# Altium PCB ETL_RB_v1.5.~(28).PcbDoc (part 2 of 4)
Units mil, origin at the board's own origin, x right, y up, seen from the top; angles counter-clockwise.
Board outline 5129.92 x 2224.41 mil, 8 copper layers (Top Layer, plane 1, M1, plane 2, plane 3, M2, plane 4, Bottom Layer), stack 36.907 mil thick; 212 components, 186 nets, 1961 pads, 978 vias.
Unrouted connection lines stored in the file: 395.
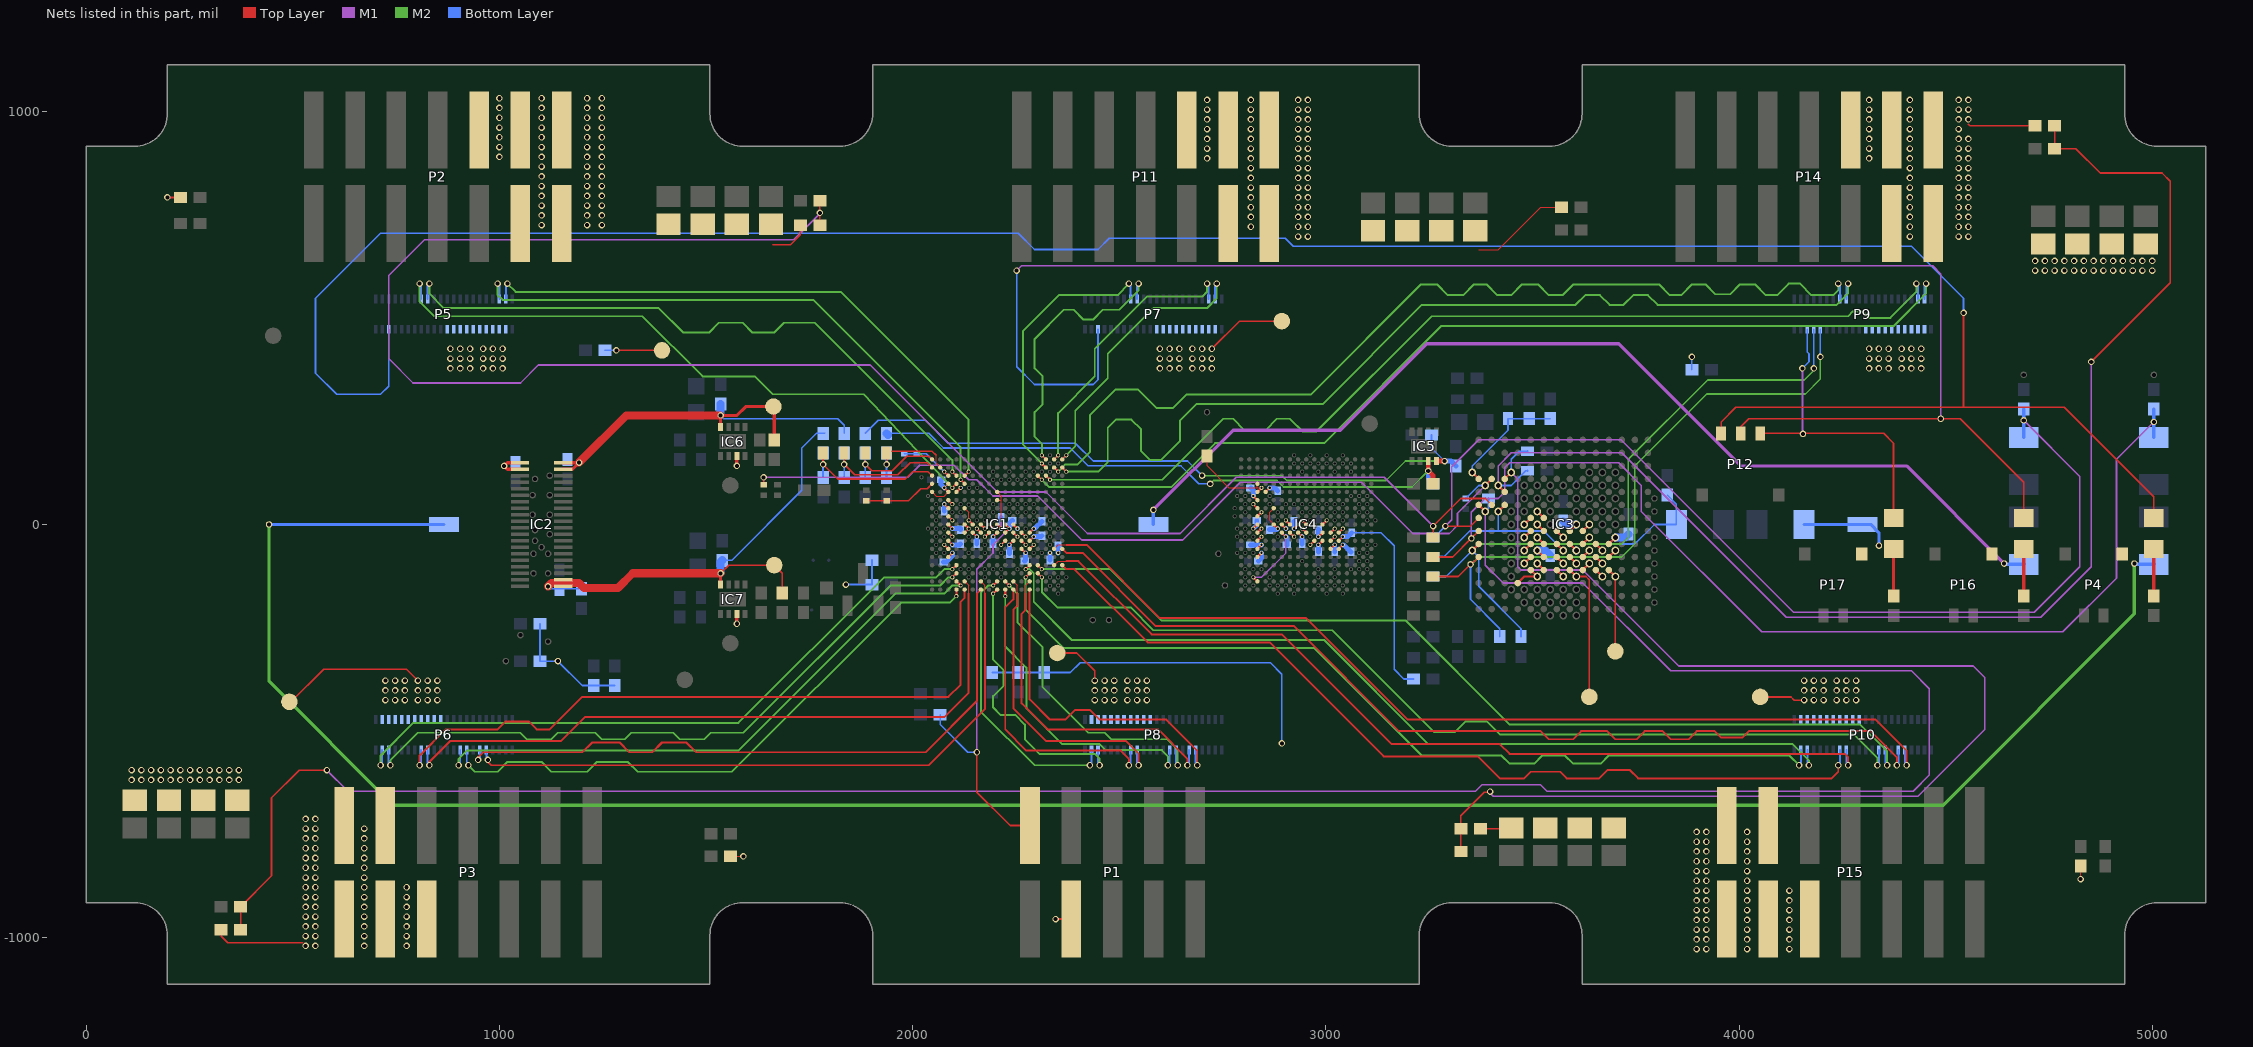
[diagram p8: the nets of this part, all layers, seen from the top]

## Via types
v1: diameter 15.75, hole 9.84, Top Layer to Bottom Layer, 978 vias

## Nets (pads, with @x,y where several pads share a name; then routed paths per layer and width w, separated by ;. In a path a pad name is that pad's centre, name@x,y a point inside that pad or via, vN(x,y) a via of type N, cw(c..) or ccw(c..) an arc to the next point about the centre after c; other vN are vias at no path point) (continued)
1V2_mon4: C205.2 IC3.P10 P9.17 pad.1@3350.39,-96.46 R211.2 | length 1597.8
  Top Layer w4: C205.2@3259.84,-125.98 3320.87,-125.98 pad.1@3350.39,-96.46 3352.36,-96.46 IC3.P10@3370.08,-78.74
  M2 w4: pad.1@3350.39,-96.46 3352.36,-96.46 3370.08,-78.74 3716.54,-78.74 3748.03,-47.24 3748.03,141.73 3922,315.7 4160.68,315.7 4196.85,351.87 v1(4196.85,405.51)
  Bottom Layer w4: pad.1@3350.39,-96.46 3350.39,-181.1 3421.26,-251.97 R211.2@3421.26,-271.65 ; v1(4196.85,405.51) P9.17@4196.85,472.44
1V2_mon5: C206.2 IC3.P9 P9.18 pad.1@3354.33,-62.99 R213.2 | length 1618.2
  Top Layer w5.12: pad.1@3354.33,-62.99 IC3.P9@3370.08,-47.24
  M2 w4: pad.1@3354.33,-62.99 3370.08,-47.24 3716.54,-47.24 3732.28,-31.5 3732.28,157.48 3924.46,349.65 4158.22,349.65 4181.1,372.54 v1(4181.1,377.95)
  Bottom Layer w4: C206.2@3259.84,-125.98 3291.34,-125.98 pad.1@3354.33,-62.99 3370.08,-78.74 3370.08,-149.61 3472.44,-251.97 R213.2@3472.44,-271.65 ; v1(4181.1,377.95) P9.18@4181.1,472.44
1V2_RB: C111.1 C112.1 C113.1 C114.1 C115.1 C116.1 C117.1 C118.1 C119.1 C120.1 C121.1 C122.1 C123.1 C124.1 C125.1 C126.1 C127.1 C128.1 C129.1 C130.1 C131.1 C132.1 C133.1 C134.1 C135.1 C160.1 C162.1 C163.1 C164.1 C165.1 C166.1 C167.1 C168.1 IC1.D3 IC1.E1 IC1.E3 IC1.E4 IC1.E9 IC1.F3 IC1.F9 IC1.G3 IC1.G5 IC1.H3 IC1.J3 IC1.J5 IC1.J6 IC1.J7 IC1.J8 IC1.J9 IC1.J11 IC1.K3 IC1.K5 IC1.K6 IC1.K7 IC1.K8 IC1.K9 IC1.K11 IC1.K12 IC1.K13 IC1.L3 IC1.L10 IC1.L11 IC1.L12 IC1.L13 IC1.M3 IC1.M12 IC1.M13 IC1.N3 IC2.38 IC2.40 IC4.D3 IC4.E3 IC4.E4 IC4.F3 IC4.G3 IC4.G5 IC4.H3 IC4.J3 IC4.J5 IC4.J6 IC4.J7 IC4.J8 IC4.J9 IC4.J11 IC4.K3 IC4.K6 IC4.K7 IC4.K8 IC4.K9 IC4.K11 IC4.K12 IC4.K13 IC4.L3 IC4.L10 IC4.L11 IC4.L12 IC4.L13 IC4.M3 IC4.M12 IC4.M13 IC4.N3 IC4.T3 IC6.3 IC7.3 P1.8 P11.10 P11.11 P11.12 P11.13 P11.14 pad.1@1011.81,141.73 pad.1@1141.73,-330.71 pad.1@2076.77,49.21 pad.1@2076.77,88.58 pad.1@2076.77,-49.21 pad.1@2096.46,9.84 pad.1@2096.46,49.21 pad.1@2096.46,-9.84 pad.1@2096.46,-29.53 pad.1@2096.46,-49.21 pad.1@2096.46,-68.9 pad.1@2116.14,88.58 pad.1@2135.83,9.84 pad.1@2135.83,-9.84 pad.1@2155.51,-9.84 pad.1@2155.51,-29.53 pad.1@2175.2,-9.84 pad.1@2175.2,-29.53 pad.1@2194.88,-9.84 pad.1@2194.88,-29.53 pad.1@2214.57,-9.84 pad.1@2214.57,-49.21 pad.1@2234.25,-49.21 pad.1@2253.94,-9.84 pad.1@2253.94,-29.53 pad.1@2273.62,-29.53 pad.1@2273.62,-49.21 pad.1@2273.62,-68.9 pad.1@2293.31,-9.84 pad.1@2293.31,-29.53 pad.1@2293.31,-49.21 pad.1@2332.68,-68.9 pad.1@2352.36,-68.9 pad.1@2824.8,49.21 pad.1@2824.8,68.9 pad.1@2824.8,-9.84 pad.1@2824.8,-127.95 pad.1@2844.49,29.53 pad.1@2844.49,88.58 pad.1@2844.49,-9.84 pad.1@2844.49,-29.53 pad.1@2844.49,-49.21 pad.1@2844.49,-68.9 pad.1@2864.17,88.58 pad.1@2883.86,-9.84 pad.1@2903.54,9.84 pad.1@2903.54,-9.84 pad.1@2903.54,-29.53 pad.1@2923.23,-9.84 pad.1@2923.23,-29.53 pad.1@2942.91,9.84 pad.1@2942.91,-9.84 pad.1@2942.91,-29.53 pad.1@2962.6,-49.21 pad.1@2982.28,-29.53 pad.1@2982.28,-49.21 pad.1@3001.97,9.84 pad.1@3021.65,-9.84 pad.1@3021.65,-29.53 pad.1@3021.65,-49.21 pad.1@3041.34,-9.84 pad.1@3041.34,-29.53 pad.1@3041.34,-49.21 R101.2 R102.1 R103.2 R104.2 R105.2 R106.2 R107.1 R109.2 R110.2 R202.2 R204.2 R206.2 R208.2 R210.2 R237.2 R238.2 R239.2 TP6.1 | length 4476.8
  Top Layer w3: R204.2@1559.06,-803.15 v1(1590.55,-803.15) ; IC1.E1@2047.24,78.74 2057.09,68.9 2076.77,68.9 IC1.E3@2086.61,78.74 ; pad.1@2076.77,88.58 IC1.D3@2086.61,98.43 ; IC1.K5@2125.98,-19.68 pad.1@2135.83,-9.84 ; IC1.G5@2125.98,39.37 2135.83,29.53 pad.1@2135.83,9.84 ; IC1.F9@2204.72,59.06 2214.57,59.06 ; IC1.E9@2204.72,78.74 2214.57,68.9 2214.57,59.06 ; pad.1@2214.57,-9.84 2214.57,59.06 ; v1(2346.46,-954.72) v1@2350.39,-954.72 ; R238.2@2712.6,165.35 2712.6,141.73 2765.75,88.58 2834.65,88.58 ; IC4.D3@2834.65,98.43 2834.65,88.58 ; pad.1@2844.49,88.58 2834.65,88.58 ; IC4.J5@2874.02,0 2864.17,9.84 2864.17,29.53 IC4.G5@2874.02,39.37 ; 3370.08,665.35 3417.32,665.35 3519.68,767.72 R206.2@3570.87,767.72 ; v1(4826.77,-858.27) R208.2@4826.77,-826.77
  Top Layer w4: v1(196.85,791.34) R202.2@228.35,791.34 ; v1(1283.46,421.26) TP6.1@1393.7,421.26
  Top Layer w4.02: v1(2346.46,-954.72) P1.8@2384.25,-954.72
  Top Layer w5.12: pad.1@2076.77,-49.21 IC1.M3@2086.61,-59.05 ; pad.1@2076.77,49.21 IC1.G3@2086.61,39.37 ; pad.1@2076.77,88.58 IC1.E3@2086.61,78.74 ; IC1.N3@2086.61,-78.74 pad.1@2096.46,-68.9 ; IC1.L3@2086.61,-39.37 pad.1@2096.46,-49.21 ; IC1.K3@2086.61,-19.68 pad.1@2096.46,-29.53 ; IC1.J3@2086.61,0 pad.1@2096.46,-9.84 ; IC1.H3@2086.61,19.69 pad.1@2096.46,9.84 ; IC1.F3@2086.61,59.06 pad.1@2096.46,49.21 ; IC1.E4@2106.3,78.74 pad.1@2116.14,88.58 ; IC1.J5@2125.98,0 pad.1@2135.83,-9.84 ; pad.1@2135.83,9.84 IC1.J6@2145.67,0 ; IC1.K6@2145.67,-19.68 pad.1@2155.51,-29.53 ; pad.1@2155.51,-9.84 IC1.K7@2165.35,-19.68 ; IC1.J7@2165.35,0 pad.1@2175.2,-9.84 ; pad.1@2175.2,-29.53 IC1.K8@2185.04,-19.68 ; IC1.J8@2185.04,0 pad.1@2194.88,-9.84 ; pad.1@2194.88,-29.53 IC1.K9@2204.72,-19.68 ; IC1.J9@2204.72,0 pad.1@2214.57,-9.84 ; pad.1@2214.57,-49.21 IC1.L10@2224.41,-39.37 ; pad.1@2234.25,-49.21 IC1.L11@2244.09,-39.37 ; IC1.K11@2244.09,-19.68 pad.1@2253.94,-29.53 ; IC1.J11@2244.09,0 pad.1@2253.94,-9.84 ; IC1.M12@2263.78,-59.05 pad.1@2273.62,-68.9 ; IC1.L12@2263.78,-39.37 pad.1@2273.62,-49.21 ; IC1.K12@2263.78,-19.68 pad.1@2273.62,-29.53 ; IC1.M13@2283.46,-59.05 pad.1@2293.31,-49.21 ; IC1.L13@2283.46,-39.37 pad.1@2293.31,-29.53 ; IC1.K13@2283.46,-19.68 pad.1@2293.31,-9.84 ; pad.1@2824.8,-127.95 IC4.T3@2834.65,-137.8 ; pad.1@2824.8,-9.84 IC4.J3@2834.65,0 ; pad.1@2824.8,49.21 IC4.G3@2834.65,39.37 ; pad.1@2824.8,68.9 IC4.F3@2834.65,59.05 ; IC4.N3@2834.65,-78.74 pad.1@2844.49,-68.9 ; IC4.M3@2834.65,-59.05 pad.1@2844.49,-49.21 ; IC4.L3@2834.65,-39.37 pad.1@2844.49,-29.53 ; IC4.K3@2834.65,-19.68 pad.1@2844.49,-9.84 ; IC4.H3@2834.65,19.68 pad.1@2844.49,29.53 ; IC4.E3@2834.65,78.74 pad.1@2844.49,88.58 ; IC4.E4@2854.33,78.74 pad.1@2864.17,88.58 ; IC4.J5@2874.02,0 pad.1@2883.86,-9.84 ; IC4.K6@2893.7,-19.68 pad.1@2903.54,-29.53 ; IC4.J6@2893.7,0 pad.1@2903.54,-9.84 ; pad.1@2903.54,9.84 IC4.J7@2913.39,0 ; IC4.K7@2913.39,-19.68 pad.1@2923.23,-29.53 ; pad.1@2923.23,-9.84 IC4.J8@2933.07,0 ; IC4.K8@2933.07,-19.68 pad.1@2942.91,-29.53 ; pad.1@2942.91,-9.84 IC4.K9@2952.76,-19.68 ; pad.1@2942.91,9.84 IC4.J9@2952.76,0 ; pad.1@2962.6,-49.21 IC4.L10@2972.44,-39.37 ; pad.1@2982.28,-49.21 IC4.L11@2992.13,-39.37 ; pad.1@2982.28,-29.53 IC4.K11@2992.13,-19.68 ; IC4.J11@2992.13,0 pad.1@3001.97,9.84 ; IC4.M12@3011.81,-59.05 pad.1@3021.65,-49.21 ; IC4.L12@3011.81,-39.37 pad.1@3021.65,-29.53 ; IC4.K12@3011.81,-19.68 pad.1@3021.65,-9.84 ; IC4.M13@3031.5,-59.05 pad.1@3041.34,-49.21 ; IC4.L13@3031.5,-39.37 pad.1@3041.34,-29.53 ; IC4.K13@3031.5,-19.68 pad.1@3041.34,-9.84
  Top Layer w7.87: IC2.38@1050,133.86 1019.69,133.86 pad.1@1011.81,141.73 1019.69,149.61 IC2.40@1050,149.61 ; v1(1574.8,-240.16) IC7.3@1574.8,-216.54 ; v1(1574.8,141.73) IC6.3@1574.8,165.35
  M1 w4: pad.1@2824.8,-127.95 2844.49,-127.95 2903.54,-68.9 pad.1@2903.54,-29.53
  Bottom Layer w3: C133.1@2817.32,88.58 C133.1@2818.9,88.58
  Bottom Layer w4: R239.2@1255.91,421.26 v1(1283.46,421.26) ; R110.2@2192.91,-358.27 R109.2@2255.91,-358.27 R210.2@2318.9,-358.27 2381.89,-358.27 2405.51,-334.65 2866.14,-334.65 2893.7,-362.2 v1(2893.7,-529.66) ; R237.2@3885.83,374.02 3885.83,377.95 v1(3885.83,405.51)
  Bottom Layer w4.02: R104.2@1098.43,-240.16 R103.2@1098.43,-330.71 pad.1@1141.73,-330.71 1200.79,-389.76 R105.2@1228.35,-389.76 R106.2@1279.53,-389.76 ; C166.1@3062.99,-20.08 3063.39,-19.68 3133.86,-19.68 3165.35,-51.18 3165.35,-350.39 3188.98,-374.02 R107.1@3212.6,-374.02
  Bottom Layer w5.12: v1(1838.58,-145.67) R101.2@1901.57,-145.67 R102.1@1901.57,-86.61 ; pad.1@2824.8,-9.84 pad.1@2826.77,-7.87
  Bottom Layer w7.87: pad.1@2116.14,88.58 pad.1@2117.72,88.58 ; C113.1@2352.36,-51.57 2353.94,-51.57 C113.1@2354.33,-51.18
  Bottom Layer w11.81: C119.1@2069.29,108.27 2069.29,96.06 pad.1@2076.77,88.58 ; C125.1@2075.2,-90.55 2082.68,-90.55 2096.46,-76.77 pad.1@2096.46,-68.9 ; C116.1@2076.77,31.89 pad.1@2076.77,49.21 ; pad.1@2096.46,-49.21 2113.78,-49.21 C117.1@2116.14,-46.85 ; pad.1@2096.46,-9.84 2116.14,-9.84 C126.1@2116.14,-12.2 ; C114.1@2155.51,-46.85 pad.1@2155.51,-29.53 ; C122.1@2194.88,-46.85 pad.1@2194.88,-29.53 ; pad.1@2214.57,-9.84 C120.1@2214.57,17.32 ; C118.1@2234.25,-70.47 pad.1@2234.25,-49.21 ; C123.1@2271.65,-88.58 C123.1@2271.26,-88.58 2273.62,-86.22 pad.1@2273.62,-68.9 ; pad.1@2293.31,-29.53 2310.63,-29.53 C115.1@2312.99,-27.17 ; pad.1@2293.31,-9.84 2295.67,-9.84 2299.56,-5.95 2299.85,-5.95 2309.1,3.3 2309.1,3.59 C124.1@2312.99,7.48 ; C121.1@2332.68,-86.22 pad.1@2332.68,-68.9 ; pad.1@2352.36,-68.9 C113.1@2352.36,-51.57 ; C130.1@2817.32,-49.21 pad.1@2844.49,-49.21 ; C133.1@2818.9,88.58 2824.8,82.68 pad.1@2824.8,68.9 ; pad.1@2826.77,-7.87 2833.07,-1.57 C164.1@2833.07,9.84 ; C132.1@2837.01,-88.58 2844.49,-81.1 pad.1@2844.49,-68.9 ; C163.1@2864.17,-12.2 2881.5,-12.2 pad.1@2883.86,-9.84 ; pad.1@2864.17,88.58 2876.38,88.58 C167.1@2883.86,81.1 ; pad.1@2903.54,-29.53 2905.91,-31.89 C168.1@2905.91,-49.21 ; pad.1@2923.23,-9.84 C129.1@2923.23,7.48 ; C128.1@2942.91,-46.85 pad.1@2942.91,-29.53 ; C134.1@2982.28,-66.54 pad.1@2982.28,-49.21 ; pad.1@2982.28,-29.53 C131.1@2982.28,-12.2 ; C165.1@3021.65,-66.54 pad.1@3021.65,-49.21 ; pad.1@3041.34,-49.21 3043.31,-49.21 3061.02,-66.93 C135.1@3061.02,-66.54 ; pad.1@3041.34,-29.53 3053.54,-29.53 C166.1@3062.99,-20.08
  other v1: 2933.07,696.85 2956.69,696.85 2818.9,720.47 2933.07,720.47 2956.69,720.47 2818.9,744.09 2933.07,744.09 2956.69,744.09 2818.9,767.72 2933.07,767.72 2956.69,767.72 2818.9,791.34 2933.07,791.34 2956.69,791.34 2818.9,814.96 2933.07,814.96 2956.69,814.96 2818.9,838.58 2933.07,838.58 2956.69,838.58 2818.9,862.2 2933.07,862.2 2956.69,862.2 2712.6,885.83 2818.9,885.83 2933.07,885.83 2956.69,885.83 2712.6,909.45 2818.9,909.45 2933.07,909.45 2956.69,909.45 2712.6,933.07 2818.9,933.07 2933.07,933.07 2956.69,933.07 2712.6,956.69 2818.9,956.69 2933.07,956.69 2956.69,956.69 2712.6,980.32 2818.9,980.32 2933.07,980.32 2956.69,980.32 2712.6,1003.94 2818.9,1003.94 2933.07,1003.94 2956.69,1003.94 2712.6,1027.56 2818.9,1027.56 2933.07,1027.56 2956.69,1027.56
1V2A: C218.1 C219.1 C220.1 C221.1 P2.10 P2.11 P2.12 P2.13 P2.14 P5.1 P5.2 P5.3 P5.4 P5.5 P5.6 P5.7 P5.8 P5.9 P5.10 P6.6 P6.7 P6.8 P6.9 P6.10 R214.2 TP1.1 | length 455.4
  Top Layer w4: TP1.1@492.13,-429.13 496.06,-429.13 574.8,-350.39 775.59,-350.39 v1(803.15,-377.95) ; 1661.42,677.17 1704.72,677.17 1728.35,700.79 R214.2@1728.35,724.41
  other v1: 803.15,-425.2 826.77,-425.2 850.39,-425.2 803.15,-401.57 826.77,-401.57 850.39,-401.57 826.77,-377.95 850.39,-377.95 881.89,377.95 905.51,377.95 929.13,377.95 960.63,377.95 984.25,377.95 1007.87,377.95 881.89,401.57 905.51,401.57 929.13,401.57 960.63,401.57 984.25,401.57 1007.87,401.57 881.89,425.2 905.51,425.2 929.13,425.2 960.63,425.2 984.25,425.2 1007.87,425.2 1102.36,724.41 1212.6,724.41 1248.03,724.41 1102.36,748.03 1212.6,748.03 1248.03,748.03 1102.36,771.65 1212.6,771.65 1248.03,771.65 1102.36,795.28 1212.6,795.28 1248.03,795.28 1102.36,818.9 1212.6,818.9 1248.03,818.9 1102.36,842.52 1212.6,842.52 1248.03,842.52 1102.36,866.14 1212.6,866.14 1248.03,866.14 1000,889.76 1102.36,889.76 1212.6,889.76 1248.03,889.76 1000,913.39 1102.36,913.39 1212.6,913.39 1248.03,913.39 1000,937.01 1102.36,937.01 1212.6,937.01 1248.03,937.01 1000,960.63 1102.36,960.63 1212.6,960.63 1248.03,960.63 1000,984.25 1102.36,984.25 1212.6,984.25 1248.03,984.25 1000,1007.87 1102.36,1007.87 1212.6,1007.87 1248.03,1007.87 1000,1031.5 1102.36,1031.5 1212.6,1031.5 1248.03,1031.5
1V2B: C222.1 C223.1 C224.1 C225.1 P3.10 P3.11 P3.12 P3.13 P3.14 P6.1 P6.2 P6.3 P6.4 P6.5 P8.1 P8.2 P8.3 P8.4 P8.5 P8.6 P8.7 P8.8 P8.9 P8.10 R216.2 TP2.1 | length 351.2
  Top Layer w4: TP2.1@2350.39,-311.02 2397.64,-311.02 2440.94,-354.33 v1(2440.94,-377.95)
  Top Layer w4.02: R216.2@326.77,-980.32 326.77,-996.06 342.52,-1011.81 523.62,-1011.81
  other v1: 531.5,-1019.68 555.12,-1019.68 673.23,-1019.68 775.59,-1019.68 531.5,-996.06 555.12,-996.06 673.23,-996.06 775.59,-996.06 531.5,-972.44 555.12,-972.44 673.23,-972.44 775.59,-972.44 531.5,-948.82 555.12,-948.82 673.23,-948.82 775.59,-948.82 531.5,-925.2 555.12,-925.2 673.23,-925.2 775.59,-925.2 531.5,-901.57 555.12,-901.57 673.23,-901.57 775.59,-901.57 531.5,-877.95 555.12,-877.95 673.23,-877.95 775.59,-877.95 531.5,-854.33 555.12,-854.33 673.23,-854.33 531.5,-830.71 555.12,-830.71 673.23,-830.71 531.5,-807.09 555.12,-807.09 673.23,-807.09 531.5,-783.46 555.12,-783.46 673.23,-783.46 531.5,-759.84 555.12,-759.84 673.23,-759.84 531.5,-736.22 555.12,-736.22 673.23,-736.22 531.5,-712.6 555.12,-712.6 110.24,-618.11 133.86,-618.11 157.48,-618.11 181.1,-618.11 204.72,-618.11 228.35,-618.11 251.97,-618.11 275.59,-618.11 299.21,-618.11 322.83,-618.11 346.46,-618.11 370.08,-618.11 110.24,-594.49 133.86,-594.49 157.48,-594.49 181.1,-594.49 204.72,-594.49 228.35,-594.49 251.97,-594.49 275.59,-594.49 299.21,-594.49 322.83,-594.49 346.46,-594.49 370.08,-594.49 724.41,-425.2 748.03,-425.2 771.65,-425.2 2440.94,-425.2 2464.57,-425.2 2488.19,-425.2 2519.69,-425.2 2543.31,-425.2 2566.93,-425.2 724.41,-401.57 748.03,-401.57 771.65,-401.57 2440.94,-401.57 2464.57,-401.57 2488.19,-401.57 2519.69,-401.57 2543.31,-401.57 2566.93,-401.57 724.41,-377.95 748.03,-377.95 771.65,-377.95 2464.57,-377.95 2488.19,-377.95 2519.69,-377.95 2543.31,-377.95 2566.93,-377.95
1V2C: C226.1 C227.1 C228.1 C229.1 P7.1 P7.2 P7.3 P7.4 P7.5 P7.6 P7.7 P7.8 P7.9 P7.10 P9.1 P9.2 P9.3 P9.4 P9.5 P14.10 P14.11 P14.12 P14.13 P14.14 R218.2 TP3.1 | length 360.1
  Top Layer w4: v1(2724.41,425.2) 2791.34,492.13 TP3.1@2893.7,492.13 ; 4555.12,968.5 4559.06,964.57 R218.2@4716.54,964.57
  other v1: 2598.43,377.95 2622.05,377.95 2645.67,377.95 2677.17,377.95 2700.79,377.95 2724.41,377.95 4393.7,377.95 4417.32,377.95 4440.94,377.95 2598.43,401.57 2622.05,401.57 2645.67,401.57 2677.17,401.57 2700.79,401.57 2724.41,401.57 4393.7,401.57 4417.32,401.57 4440.94,401.57 2598.43,425.2 2622.05,425.2 2645.67,425.2 2677.17,425.2 2700.79,425.2 4393.7,425.2 4417.32,425.2 4440.94,425.2 4716.54,614.17 4740.16,614.17 4763.78,614.17 4787.4,614.17 4811.02,614.17 4834.65,614.17 4858.27,614.17 4881.89,614.17 4905.51,614.17 4929.13,614.17 4952.76,614.17 4976.38,614.17 5000,614.17 4716.54,637.8 4740.16,637.8 4763.78,637.8 4787.4,637.8 4811.02,637.8 4834.65,637.8 4858.27,637.8 4881.89,637.8 4905.51,637.8 4929.13,637.8 4952.76,637.8 4976.38,637.8 5000,637.8 4413.39,696.85 4531.5,696.85 4555.12,696.85 4413.39,720.47 4531.5,720.47 4555.12,720.47 4413.39,744.09 4531.5,744.09 4555.12,744.09 4413.39,767.72 4531.5,767.72 4555.12,767.72 4413.39,791.34 4531.5,791.34 4555.12,791.34 4413.39,814.96 4531.5,814.96 4555.12,814.96 4413.39,838.58 4531.5,838.58 4555.12,838.58 4413.39,862.2 4531.5,862.2 4555.12,862.2 4314.96,885.83 4413.39,885.83 4531.5,885.83 4555.12,885.83 4314.96,909.45 4413.39,909.45 4531.5,909.45 4555.12,909.45 4314.96,933.07 4413.39,933.07 4531.5,933.07 4555.12,933.07 4314.96,956.69 4413.39,956.69 4531.5,956.69 4314.96,980.32 4413.39,980.32 4531.5,980.32 4555.12,980.32 4314.96,1003.94 4413.39,1003.94 4531.5,1003.94 4555.12,1003.94 4314.96,1027.56 4413.39,1027.56 4531.5,1027.56 4555.12,1027.56
1V2D: C230.1 C231.1 C232.1 C233.1 P9.6 P9.7 P9.8 P9.9 P9.10 P10.1 P10.2 P10.3 P10.4 P10.5 P10.6 P10.7 P10.8 P10.9 P10.10 P15.10 P15.11 P15.12 P15.13 P15.14 R220.2 TP4.1 | length 185.2
  Top Layer w4: R220.2@3374.02,-736.22 3446.85,-736.22 C233.1@3448.82,-734.25 ; TP4.1@4051.18,-417.32 4125.98,-417.32 4133.86,-425.2 v1(4157.48,-425.2)
  other v1: 3897.64,-1027.56 3921.26,-1027.56 4019.69,-1027.56 4122.05,-1027.56 3897.64,-1003.94 3921.26,-1003.94 4019.69,-1003.94 4122.05,-1003.94 3897.64,-980.32 3921.26,-980.32 4019.69,-980.32 4122.05,-980.32 3897.64,-956.69 3921.26,-956.69 4019.69,-956.69 4122.05,-956.69 3897.64,-933.07 3921.26,-933.07 4019.69,-933.07 4122.05,-933.07 3897.64,-909.45 3921.26,-909.45 4019.69,-909.45 4122.05,-909.45 3897.64,-885.83 3921.26,-885.83 4019.69,-885.83 4122.05,-885.83 3897.64,-862.2 3921.26,-862.2 4019.69,-862.2 3897.64,-838.58 3921.26,-838.58 4019.69,-838.58 3897.64,-814.96 3921.26,-814.96 4019.69,-814.96 3897.64,-791.34 3921.26,-791.34 4019.69,-791.34 3897.64,-767.72 3921.26,-767.72 4019.69,-767.72 3897.64,-744.09 3921.26,-744.09 4019.69,-744.09 4181.1,-425.2 4204.72,-425.2 4236.22,-425.2 4259.84,-425.2 4283.46,-425.2 4157.48,-401.57 4181.1,-401.57 4204.72,-401.57 4236.22,-401.57 4259.84,-401.57 4283.46,-401.57 4157.48,-377.95 4181.1,-377.95 4204.72,-377.95 4236.22,-377.95 4259.84,-377.95 4283.46,-377.95 4314.96,377.95 4338.58,377.95 4362.2,377.95 4314.96,401.57 4338.58,401.57 4362.2,401.57 4314.96,425.2 4338.58,425.2 4362.2,425.2
1V5A: C138.1 C139.1 IC3.D9 IC3.D10 IC3.D11 IC3.E9 IC3.E10 IC3.E11 IC3.F8 IC3.F9 IC3.F10 IC3.F11 IC3.J7 IC3.J8 IC3.J9 IC3.J10 IC3.J11 IC3.K7 IC3.K8 IC3.K9 IC3.K10 IC3.K11 IC3.L12 IC5.7 pad.1@2720.47,98.43 pad.1@3480.31,0 pad.1@3480.31,-31.5 pad.1@3480.32,-62.99 pad.1@3480.32,-94.49 pad.1@3511.81,0 pad.1@3511.81,31.5 pad.1@3511.81,-31.5 pad.1@3511.81,-62.99 pad.1@3511.81,-94.49 pad.1@3511.81,-125.98 pad.1@3637.8,0 pad.1@3637.8,-31.5 pad.1@3637.8,-62.99 pad.1@3637.8,-94.49 pad.1@3669.29,-62.99 pad.1@3669.29,-94.49 pad.1@3669.29,-125.98 pad.1@3700.79,-31.5 pad.1@3700.79,-62.99 pad.1@3700.79,-125.98 R113.1 R128.1 R133.2 TP7.1 | length 2249.9
  Top Layer w4: TP7.1@3700.79,-307.09 pad.1@3700.79,-125.98
  Top Layer w5.12: IC3.L12@3464.57,-141.73 3480.31,-125.98 pad.1@3511.81,-125.98 IC3.K11@3496.06,-110.24 ; pad.1@3480.32,-94.49 IC3.K10@3496.06,-78.74 ; pad.1@3480.32,-62.99 IC3.K9@3496.06,-47.24 ; pad.1@3480.31,-31.5 IC3.K8@3496.06,-15.75 ; pad.1@3480.31,0 IC3.K7@3496.06,15.75 ; pad.1@3511.81,-94.49 IC3.J11@3527.56,-110.24 ; pad.1@3511.81,-62.99 IC3.J10@3527.56,-78.74 ; pad.1@3511.81,-31.5 IC3.J9@3527.56,-47.24 ; pad.1@3511.81,0 IC3.J8@3527.56,-15.75 ; pad.1@3511.81,31.5 IC3.J7@3527.56,15.75 ; IC3.F11@3622.05,-110.24 pad.1@3637.8,-94.49 ; IC3.F10@3622.05,-78.74 pad.1@3637.8,-62.99 ; IC3.F9@3622.05,-47.24 pad.1@3637.8,-31.5 ; IC3.F8@3622.05,-15.75 pad.1@3637.8,0 ; IC3.E11@3653.54,-110.24 pad.1@3669.29,-125.98 ; IC3.E10@3653.54,-78.74 pad.1@3669.29,-94.49 ; IC3.E9@3653.54,-47.24 pad.1@3669.29,-62.99 ; IC3.D11@3685.04,-110.24 pad.1@3700.79,-125.98 ; IC3.D10@3685.04,-78.74 pad.1@3700.79,-62.99 ; IC3.D9@3685.04,-47.24 pad.1@3700.79,-31.5
  Top Layer w11.81: IC5.7@3248.03,153.54 v1(3248.03,129.92) 3259.84,118.11 R113.1@3259.84,98.43 R113.1@3263.78,102.36
  M2 w4: pad.1@2720.47,98.43 2728.35,106.3 2881.89,106.3 2897.64,90.55 3208.66,90.55 v1(3248.03,129.92)
  Bottom Layer w4: R133.2@1940.94,216.54 1944.88,220.47 2039.37,220.47 2074.8,185.04 2381.89,185.04 2425.2,141.73 2649.61,141.73 2692.91,98.43 pad.1@2720.47,98.43
  Bottom Layer w11.81: v1(3248.03,129.92) 3248.03,110.24 R128.1@3259.84,98.43 R128.1@3263.78,102.36
  Bottom Layer w18.9: R133.2@1937.01,220.47 R133.2@1940.94,216.54 ; pad.1@3511.81,-62.99 3531.5,-62.99 C138.1@3543.31,-74.8 ; pad.1@3700.79,-31.5 3724.41,-31.5 C139.1@3732.28,-23.62
1V5D: C140.1 IC3.G8 IC3.G9 IC3.G10 IC3.G11 IC3.H8 IC3.H9 IC3.H10 IC3.H11 IC5.8 pad.1@2700.79,118.11 pad.1@3574.8,-31.5 pad.1@3574.8,-62.99 pad.1@3574.8,-94.49 pad.1@3574.8,-125.98 pad.1@3606.3,0 pad.1@3606.3,-62.99 pad.1@3606.3,-94.49 pad.1@3606.3,-125.98 R111.1 R117.2 R127.1 TP8.1 | length 2153.9
  Top Layer w4: pad.1@3606.3,-125.98 3629.92,-125.98 3637.8,-133.86 TP8.1@3637.8,-417.32
  Top Layer w5.12: IC3.H11@3559.05,-110.24 pad.1@3574.8,-125.98 ; IC3.H10@3559.05,-78.74 pad.1@3574.8,-94.49 ; IC3.H9@3559.05,-47.24 pad.1@3574.8,-62.99 ; IC3.H8@3559.05,-15.75 pad.1@3574.8,-31.5 ; IC3.G11@3590.55,-110.24 pad.1@3606.3,-125.98 ; IC3.G10@3590.55,-78.74 pad.1@3606.3,-94.49 ; IC3.G9@3590.55,-47.24 pad.1@3606.3,-62.99 ; IC3.G8@3590.55,-15.75 pad.1@3606.3,0
  Top Layer w11.81: IC5.8@3267.72,153.54 v1(3287.4,153.54)
  M2 w4: pad.1@2700.79,118.11 2893.7,118.11 2905.51,106.3 3145.67,106.3 3192.91,153.54 v1(3287.4,153.54)
  Bottom Layer w4: R117.2@1885.83,220.47 1917.32,251.97 2031.5,251.97 2086.61,196.85 2393.7,196.85 2437.01,153.54 2665.35,153.54 pad.1@2700.79,118.11 ; R127.1@3255.91,216.54 3255.91,185.04 v1(3287.4,153.54)
  Bottom Layer w11.81: v1(3287.4,153.54) 3303.15,153.54 R111.1@3314.96,141.73
  Bottom Layer w18.9: C140.1@3574.8,7.87 3582.68,0 pad.1@3606.3,0
2V5F: C136.1 IC1.J10 IC1.K10 P1.9 pad.1@2234.25,-9.84 R132.1 | length 1023.1
  Top Layer w4: v1(2155.51,-551.18) 2155.51,-647.64 2236.22,-728.35 P1.9@2284.25,-728.35
  Top Layer w5.12: IC1.K10@2224.41,-19.68 pad.1@2234.25,-9.84 IC1.J10@2224.41,0
  M1 w4: v1(2155.51,-551.18) 2155.51,-108.27 2194.88,-68.9 2194.88,-49.21 pad.1@2234.25,-9.84
  Bottom Layer w4: R132.1@2066.93,-460.63 2066.93,-484.25 2133.86,-551.18 v1(2155.51,-551.18)
  Bottom Layer w11.81: pad.1@2234.25,-9.84 2234.25,2.36 C136.1@2241.73,9.84
2V5RX: C154.1 IC2.1 IC2.3 IC7.8 pad.1@1118.11,-149.61 R124.1 R125.2 R135.2 R148.2 TP9.1 | length 1236.3
  Top Layer w4: v1(1535.43,-118.11) 1555.12,-98.43 TP9.1@1665.35,-98.43 1685.04,-118.11 R124.1@1685.04,-165.35
  Top Layer w7.87: IC7.8@1535.43,-145.67 v1(1535.43,-118.11)
  Top Layer w19.68: pad.1@1118.11,-149.61 1125.98,-141.73 1192.91,-141.73 1204.72,-153.54 1287.4,-153.54 1322.83,-118.11 v1(1535.43,-118.11)
  Bottom Layer w4: pad.1@1118.11,-149.61 1124.02,-155.51 R148.2@1198.82,-155.51 ; R125.2@1539.37,-86.61 1562.99,-86.61 1732.28,82.68 1732.28,185.04 1767.72,220.47 R135.2@1783.46,220.47 ; R135.2@1783.46,220.47 1787.4,220.47 R135.2@1783.46,220.47
  Bottom Layer w19.68: v1(1535.43,-118.11) 1535.43,-90.55 R125.2@1539.37,-86.61
2V5TX: C153.1 IC2.37 IC2.39 IC6.8 R114.2 R116.1 R119.2 TP10.1 | length 1075
  Top Layer w7.87: IC2.37@1154.72,133.86 1177.17,133.86 v1(1192.91,149.61) IC2.39@1154.72,149.61 ; IC6.8@1535.43,236.22 v1(1535.43,263.78) 1574.8,263.78 1596.46,285.43 TP10.1@1663.39,285.43 1665.35,283.46 R116.1@1665.35,204.72
  Top Layer w19.68: v1(1192.91,149.61) 1307.09,263.78 v1(1535.43,263.78)
  Bottom Layer w4: v1(1535.43,263.78) 1543.31,255.91 1818.9,255.91 1834.65,240.16 R119.2@1834.65,220.47
  Bottom Layer w19.68: v1(1535.43,263.78) R114.2@1535.43,291.34
ADC1: C109.1 IC1.A1 R117.1 R118.2 | length 272.5
  Top Layer w3: v1(1885.83,145.67) C109.1@1885.83,173.23
  Top Layer w4: v1(1885.83,145.67) 1901.57,129.92 1950.79,129.92 1986.22,165.35 2039.37,165.35 IC1.A1@2047.24,157.48
  Bottom Layer w4: R118.2@1885.83,114.17 v1(1885.83,145.67) R117.1@1885.83,173.23
ADC2: C141.1 IC1.B2 R133.1 R134.2 | length 246
  Top Layer w3: v1(1937.01,145.67) C141.1@1937.01,173.23 ; 2057.09,167.32 2057.09,147.64 IC1.B2@2066.93,137.8
  Top Layer w4: C141.1@1937.01,173.23 1940.94,177.17 2047.24,177.17 2057.09,167.32
  Bottom Layer w4: R134.2@1937.01,114.17 v1(1937.01,145.67) R133.1@1937.01,173.23
ADC3: C150.1 IC1.B1 R119.1 R120.2 | length 326.9
  Top Layer w4: C150.1@1834.65,173.23 v1(1834.65,145.67) 1860.24,120.08 1964.57,120.08 1994.09,149.61 2035.43,149.61 IC1.B1@2047.24,137.8
  Bottom Layer w4: R120.2@1834.65,114.17 v1(1834.65,145.67) R119.1@1834.65,173.23
ADC4: IC1.C3 pad.1@2076.77,127.95 R146.2 R147.1 | length 128.3
  Top Layer w5.12: pad.1@2076.77,127.95 IC1.C3@2086.61,118.11
  Bottom Layer w4: R147.1@1980.31,171.26 R146.2@2009.84,171.26 2033.46,171.26 pad.1@2076.77,127.95
ADC6: C151.1 IC1.C1 R122.2 R135.1 | length 376.5
  Top Layer w4: C151.1@1783.46,173.23 v1(1783.46,145.67) 1818.9,110.24 1982.28,110.24 2000,127.95 2037.4,127.95 IC1.C1@2047.24,118.11
  Bottom Layer w4: R122.2@1783.46,114.17 v1(1783.46,145.67) R135.1@1783.46,173.23
ADC7: IC1.D1 R145.1 RT1.2 | length 176.6
  Top Layer w4: RT1.2@1887.8,57.09 R145.1@1937.01,57.09 1990.16,57.09 2019.69,86.61 2035.43,86.61 IC1.D1@2047.24,98.43
ADC_IN18: C207.2 IC3.P8 pad.1@3352.36,-33.46 pad.1@5003.94,248.03 R222.1 R223.2 | length 2589.3
  Top Layer w4: C207.2@3259.84,-78.74 3307.09,-78.74 pad.1@3352.36,-33.46 IC3.P8@3370.08,-15.75
  M1 w4: pad.1@3352.36,-33.46 3352.36,29.53 3385.83,62.99 3417.32,62.99 3433.07,78.74 3433.07,137.8 3444.88,149.61 3708.66,149.61 3763.78,94.49 3763.78,31.5 4055.12,-259.84 4783.46,-259.84 4913.39,-129.92 4913.39,157.48 pad.1@5003.94,248.03
  Bottom Layer w8: R222.1@5003.94,210.63 R223.2@5003.94,279.53
ADC_IN21: C208.2 IC3.P7 pad.1@4688.98,251.97 R224.1 R225.2 | length 2524.6
  Top Layer w4.02: v1(3289.37,-3.94) 3350.39,-3.94 IC3.P7@3370.08,15.75
  M1 w4.02: v1(3289.37,-3.94) 3305.12,11.81 3305.12,139.76 3370.08,204.72 3714.57,204.72 4131.89,-212.6 4714.57,-212.6 4824.8,-102.36 4824.8,116.14 pad.1@4688.98,251.97
  Bottom Layer w4.02: C208.2@3259.84,-31.5 3261.81,-31.5 v1(3289.37,-3.94)
  Bottom Layer w8: R224.1@4688.98,210.63 R225.2@4688.98,279.53
ADC_IN22: C209.2 IC3.M6 pad.1@3417.32,31.5 R226.1 R227.2 | length 799.4
  Top Layer w5.12: pad.1@3417.32,31.5 IC3.M6@3433.07,47.24
  Bottom Layer w4: C209.2@3259.84,-78.74 3259.84,-76.77 3283.46,-76.77 3285.43,-78.74 3348.43,-15.75 3417.32,-15.75 ; pad.1@3417.32,31.5 3417.32,-15.75 ; R227.2@3826.77,70.87 3848.43,49.21 R226.1@3848.43,0 3795.28,0 3748.03,-47.24 3559.06,-47.24 3527.56,-15.75 3417.32,-15.75
ADC_IN23: C210.2 IC3.N6 R214.1 R215.2 | length 4413.5
  Top Layer w4: R214.1@1775.59,724.41 v1(1775.59,753.94) R215.2@1775.59,783.46 ; C210.2@3259.84,-31.5 v1(3259.84,-3.94) ; v1@3260.61,-3.17 3326.77,62.99 3385.83,62.99 IC3.N6@3401.57,47.24
  M1 w4: v1(1775.59,753.94) 1775.59,751.97 1712.6,688.98 818.9,688.98 732.28,602.36 732.28,401.57 791.34,342.52 1051.18,342.52 1094.49,385.83 1897.64,385.83 2204.72,78.74 2322.83,78.74 2423.23,-21.65 2647.64,-21.65 2783.46,114.17 3141.73,114.17 v1(3259.84,-3.94)
ADC_IN24: C211.2 IC3.P6 pad.1@3385.83,31.5 R216.1 R217.2 | length 6034.3
  Top Layer w4.02: R216.1@374.02,-980.32 R217.2@374.02,-925.2 448.82,-850.39 448.82,-661.42 515.75,-594.49 v1(582.68,-594.49)
  Top Layer w5.12: IC3.P6@3370.08,47.24 pad.1@3385.83,31.5
  M1 w4.02: v1(582.68,-594.49) 633.86,-645.67 3362.2,-645.67 3377.95,-629.92 3519.69,-629.92 3535.43,-645.67 4421.26,-645.67 4460.63,-606.3 4460.63,-397.64 4417.32,-354.33 3834.65,-354.33 3622.05,-141.73 3429.13,-141.73 3385.83,-98.43 pad.1@3385.83,31.5
  Bottom Layer w4: pad.1@3385.83,31.5 3393.7,39.37 C211.2@3393.7,62.99
ADC_IN25: C212.2 IC3.M5 pad.1@3417.32,94.49 R218.1 R219.2 | length 3197.8
  Top Layer w4.02: R218.1@4763.78,964.57 R219.2@4763.78,909.45 4814.96,909.45 4874.02,850.39 5023.62,850.39 5043.31,830.71 5043.31,584.65 v1(4852.36,393.7)
  Top Layer w5.12: pad.1@3417.32,94.49 IC3.M5@3433.07,78.74
  M1 w4.02: pad.1@3417.32,94.49 3417.32,141.73 3448.82,173.23 3716.54,173.23 4114.17,-224.41 4730.32,-224.41 4852.36,-102.36 v1(4852.36,393.7)
  Bottom Layer w4.02: pad.1@3417.32,94.49 3448.82,94.49 3484.25,129.92 C212.2@3488.19,129.92
ADC_IN28: C213.2 IC3.M4 pad.1@3448.82,125.98 R220.1 R221.2 | length 3154.6
  Top Layer w4.02: R221.2@3326.77,-791.34 R220.1@3326.77,-736.22 3326.77,-704.72 3383.74,-647.76 3396.43,-647.76 v1(3397.64,-646.54)
  Top Layer w5.12: IC3.M4@3433.07,110.24 pad.1@3448.82,125.98
  M1 w4.02: v1(3397.64,-646.54) 3397.64,-649.61 3405.51,-657.48 4433.07,-657.48 4594.49,-496.06 4594.49,-370.08 4566.93,-342.52 3854.33,-342.52 3622.05,-110.24 3472.44,-110.24 3464.57,-102.36 3464.57,110.24 pad.1@3448.82,125.98
  Bottom Layer w4.02: pad.1@3448.82,125.98 3448.82,157.48 3468.5,177.17 C213.2@3488.19,177.17
ADC_IN29: IC3.N4 pad.1@3385.83,94.49 R243.1 RT2.2 | length 2108.3
  Top Layer w4.02: R243.1@1639.76,96.46 v1(1639.76,114.17)
  Top Layer w5.12: pad.1@3385.83,94.49 IC3.N4@3401.57,110.24
  M1 w4.02: v1(1639.76,114.17) 1988.19,114.17 2017.72,143.7 2100.39,143.7 2135.83,108.27 2155.51,108.27 2194.88,68.9 2303.15,68.9 2409.45,-37.4 2653.54,-37.4 2793.31,102.36 3086.61,102.36 3210.63,-21.65 3299.21,-21.65 3318.9,-1.97 3318.9,27.56 pad.1@3385.83,94.49
  Bottom Layer w4.02: RT2.2@3338.58,62.99 3370.08,94.49 pad.1@3385.83,94.49
ADC_IN30: C214.2 IC3.P4 pad.1@3354.33,125.98 R228.1 R229.2 | length 290.4
  Top Layer w5.12: pad.1@3354.33,125.98 IC3.P4@3370.08,110.24
  Bottom Layer w4.02: pad.1@3354.33,125.98 3354.33,141.73 3440.94,228.35 C214.2@3440.94,255.91 R228.1@3543.31,255.91
AGND0: C215.2 P5.19 P12.3 | length 6161
  Top Layer w4: P12.3@3956.69,220.47 3956.69,248.03 3992.13,283.46 4543.31,283.46 ; v1(4543.31,511.81) 4543.31,283.46 ; C215.2@5003.94,15.75 5003.94,66.93 4787.4,283.46 4543.31,283.46
  Bottom Layer w4: P5.19@732.28,472.44 732.28,334.65 712.6,314.96 606.3,314.96 555.12,366.14 555.12,547.24 712.6,704.72 2255.91,704.72 2295.28,665.35 2448.82,665.35 2476.38,692.91 2901.57,692.91 2921.26,673.23 4417.32,673.23 4543.31,547.24 v1(4543.31,511.81)
AGND1: C216.2 P7.19 P12.2 pad.1@4488.19,255.91 | length 4032.8
  Top Layer w4: P12.2@4003.94,220.47 4003.94,236.22 4023.62,255.91 pad.1@4488.19,255.91 4535.43,255.91 4688.98,102.36 C216.2@4688.98,15.75
  M1 w4: v1(2251.97,614.17) 2263.78,625.98 4468.5,625.98 4488.19,606.3 pad.1@4488.19,255.91
  Bottom Layer w4: v1(2251.97,614.17) 2251.97,381.89 2295.28,338.58 2437.01,338.58 2448.82,350.39 P7.19@2448.82,472.44
AGND2: C217.2 P9.19 P12.1 pad.1@4154.77,219.24 | length 776.8
  Top Layer w4: P12.1@4051.18,220.47 4153.54,220.47 4350.39,220.47 4374.02,196.85 C217.2@4374.02,15.75 ; pad.1@4154.77,219.24 pad.1@4154.77,220.47
  M1 w4: v1(4153.54,377.95) 4153.54,220.47 pad.1@4154.77,219.24
  Bottom Layer w4: v1(4153.54,377.95) 4169.29,393.7 4169.29,413.39 4165.35,417.32 P9.19@4165.35,472.44
BV0: C215.1 CT1.1 P4.3 pad.1@442.91,0 pad.1@4956.69,-94.49 R230.1 R240.2 | length 5916.8
  Top Layer w8: R230.1@5003.94,-173.23 C215.1@5003.94,-59.06
  M2 w8: pad.1@442.91,0 442.91,-379.92 742.13,-679.13 4494.09,-679.13 4956.69,-216.54 pad.1@4956.69,-94.49
  Bottom Layer w8: pad.1@442.91,0 CT1.1@866.14,0 ; pad.1@4956.69,-94.49 4958.66,-96.46 R240.2@5003.94,-96.46
BV1: C216.1 CT2.1 P16.3 pad.1@2582.68,35.43 pad.1@4641.73,-94.49 R231.1 R241.2 | length 2643.2
  Top Layer w8: R231.1@4688.98,-173.23 C216.1@4688.98,-59.06
  M1 w8: pad.1@2582.68,35.43 2775.59,228.35 3035.43,228.35 3244.09,437.01 3708.66,437.01 4003.94,141.73 4405.51,141.73 pad.1@4641.73,-94.49
  Bottom Layer w8: CT2.1@2582.68,0 pad.1@2582.68,35.43 ; pad.1@4641.73,-94.49 4643.7,-96.46 R241.2@4688.98,-96.46
BV2: C217.1 CT3.1 P17.3 pad.1@4338.58,-51.18 R232.1 R242.2 | length 338.9
  Top Layer w8: R232.1@4374.02,-173.23 C217.1@4374.02,-59.06
  Bottom Layer w3: pad.1@4338.58,-55.12 pad.1@4338.58,-51.18
  Bottom Layer w8: R242.2@4157.48,0 CT3.1@4299.21,0 4318.9,0 4338.58,-19.68 pad.1@4338.58,-51.18
ECLK0N: IC1.U4 P6.27 pad.1@2106.3,-173.23 | length 1457.7
  Top Layer w5.12: pad.1@2106.3,-173.23 IC1.U4@2106.3,-157.48
  M2 w4.72: v1(925.2,-582.68) 940.94,-598.43 996.06,-598.43 1019.69,-574.8 1102.36,-574.8 1125.98,-598.43 1212.6,-598.43 1236.22,-574.8 1311.02,-574.8 1334.65,-598.43 1562.99,-598.43 1972.44,-188.98 2090.55,-188.98 pad.1@2106.3,-173.23
  Bottom Layer w4.72: P6.27@921.26,-545.28 921.26,-578.74 v1(925.2,-582.68)
ECLK0P: IC1.T4 P6.28 pad.1@2116.14,-147.64 | length 1456.9
  Top Layer w5.12: IC1.T4@2106.3,-137.79 pad.1@2116.14,-147.64
  M2 w4.72: v1(901.57,-582.68) 901.57,-566.93 921.26,-547.24 1578.74,-547.24 1958.66,-167.32 2076.77,-167.32 2096.46,-147.64 pad.1@2116.14,-147.64
  Bottom Layer w4.72: v1(901.57,-582.68) 905.51,-578.74 P6.28@905.51,-545.28
ECLK1N: IC1.R4 P6.39 pad.1@2096.46,-127.95 | length 1647.6
  Top Layer w5.12: pad.1@2096.46,-127.95 IC1.R4@2106.3,-118.11
  M2 w4.72: v1(736.22,-582.68) 736.22,-570.87 803.15,-503.94 1051.18,-503.94 1066.93,-519.68 1125.98,-519.68 1141.73,-503.94 1232.28,-503.94 1248.03,-519.68 1303.15,-519.68 1318.9,-503.94 1421.26,-503.94 1437.01,-519.68 1496.06,-519.68 1511.81,-503.94 1590.55,-503.94 1946.85,-147.64 2066.93,-147.64 2086.61,-127.95 pad.1@2096.46,-127.95
  Bottom Layer w4.72: P6.39@732.28,-545.28 732.28,-578.74 v1(736.22,-582.68)
ECLK1P: IC1.P4 P6.40 pad.1@2096.46,-108.27 | length 1647.2
  Top Layer w5.12: pad.1@2096.46,-108.27 IC1.P4@2106.3,-98.42
  M2 w4.72: v1(712.6,-582.68) 712.6,-559.06 791.34,-480.32 1578.74,-480.32 1931.1,-127.95 2057.09,-127.95 2076.77,-108.27 ; 2076.77,-108.27 pad.1@2096.46,-108.27
  Bottom Layer w4.72: v1(712.6,-582.68) 716.54,-578.74 P6.40@716.54,-545.28
ECLK2N: IC1.U9 P8.39 pad.1@2194.88,-167.32 | length 695.5
  Top Layer w5.12: pad.1@2194.88,-167.32 IC1.U9@2204.72,-157.48
  M2 w4.72: pad.1@2194.88,-167.32 2194.88,-326.77 2220.47,-352.36 2220.47,-389.76 2194.88,-415.35 2194.88,-442.91 2212.6,-460.63 2248.03,-460.63 2271.65,-484.25 2271.65,-519.68 2307.09,-555.12 2440.94,-555.12 2452.76,-566.93 v1(2452.76,-582.68)
  Bottom Layer w4.72: P8.39@2448.82,-545.28 2448.82,-578.74 v1(2452.76,-582.68)
ECLK2P: IC1.T9 P8.40 pad.1@2194.88,-147.64 | length 694.8
  Top Layer w5.12: pad.1@2194.88,-147.64 IC1.T9@2204.72,-137.79
  M2 w4.72: pad.1@2194.88,-147.64 2183.07,-147.64 2165.35,-165.35 2165.35,-452.76 2295.28,-582.68 v1(2429.13,-582.68)
  Bottom Layer w4.72: v1(2429.13,-582.68) 2433.07,-578.74 P8.40@2433.07,-545.28
ECLK3N: IC1.U10 P8.28 pad.1@2224.41,-173.23 | length 759.9
  Top Layer w5.12: pad.1@2224.41,-173.23 IC1.U10@2224.41,-157.48
  M2 w4.72: pad.1@2224.41,-173.23 2224.41,-295.28 2275.59,-346.46 2275.59,-444.88 2362.2,-531.5 2452.76,-531.5 2467.52,-546.26 2603.35,-546.26 2618.11,-561.02 v1(2618.11,-582.68)
  Bottom Layer w4.72: v1(2618.11,-582.68) 2622.05,-578.74 P8.28@2622.05,-545.28
ECLK3P: IC1.T10 P8.27 pad.1@2234.25,-147.64 | length 759.4
  Top Layer w5.12: IC1.T10@2224.41,-137.79 pad.1@2234.25,-147.64
  M2 w4.72: pad.1@2234.25,-147.64 2253.94,-167.32 2253.94,-236.22 2314.96,-297.24 2314.96,-393.7 2425.2,-503.94 2464.57,-503.94 2480.31,-519.68 2616.14,-519.68 2641.73,-545.28 v1(2641.73,-582.68)
  Bottom Layer w4.72: P8.27@2637.8,-545.28 2637.8,-578.74 v1(2641.73,-582.68)
ECLK4N: IC1.R13 P10.40 pad.1@2273.62,-127.95 | length 2192.1
  Top Layer w5.12: pad.1@2273.62,-127.95 IC1.R13@2283.46,-118.11
  M2 w4.72: pad.1@2273.62,-127.95 2273.62,-206.69 2366.14,-299.21 2972.44,-299.21 3232.28,-559.06 3425.2,-559.06 3444.88,-578.74 3503.94,-578.74 3523.62,-559.06 3578.74,-559.06 3598.43,-578.74 3665.35,-578.74 3685.04,-559.06 4122.05,-559.06 v1(4145.67,-582.68)
  Bottom Layer w4.72: v1(4145.67,-582.68) 4149.61,-578.74 P10.40@4149.61,-545.28
ECLK4P: IC1.P13 P10.39 pad.1@2273.62,-108.27 | length 2192.4
  Top Layer w5.12: pad.1@2273.62,-108.27 IC1.P13@2283.46,-98.42
  M2 w4.72: pad.1@2273.62,-108.27 2283.46,-108.27 2293.31,-118.11 2293.31,-187.01 2385.83,-279.53 2996.06,-279.53 3248.03,-531.5 4129.92,-531.5 4169.29,-570.87 v1(4169.29,-582.68)
  Bottom Layer w4.72: P10.39@4165.35,-545.28 4165.35,-578.74 v1(4169.29,-582.68)
ECLK5N: IC1.R14 P10.28 pad.1@2312.99,-127.95 | length 2315.3
  Top Layer w5.12: IC1.R14@2303.15,-118.11 pad.1@2312.99,-127.95
  M2 w4.72: pad.1@2312.99,-127.95 2312.99,-163.39 2350.39,-200.79 2527.56,-200.79 2582.68,-255.91 3015.75,-255.91 3261.81,-501.97 3312.99,-501.97 3338.58,-476.38 3389.76,-476.38 3421.26,-507.87 4277.56,-507.87 4334.65,-564.96 v1(4334.65,-582.68)
  Bottom Layer w4.72: v1(4334.65,-582.68) 4338.58,-578.74 P10.28@4338.58,-545.28
ECLK5P: IC1.P14 P10.27 pad.1@2312.99,-108.27 | length 2314.3
  Top Layer w5.12: IC1.P14@2303.15,-98.42 pad.1@2312.99,-108.27
  M2 w4.72: pad.1@2312.99,-108.27 2478.35,-108.27 2602.36,-232.28 3192.91,-232.28 3444.88,-484.25 4293.31,-484.25 4358.27,-549.21 v1(4358.27,-582.68)
  Bottom Layer w4.72: P10.27@4354.33,-545.28 4354.33,-578.74 v1(4358.27,-582.68)
ECLK22N: IC1.B17 P9.28 pad.1@2372.05,127.95 | length 2376.5
  Top Layer w5.12: IC1.B17@2362.2,137.8 pad.1@2372.05,127.95
  M2 w4.72: pad.1@2372.05,127.95 2449.8,127.95 2472.44,150.59 2472.44,234.25 2492.13,253.94 2529.53,253.94 2553.15,230.32 2553.15,177.17 2574.8,155.51 2600.39,155.51 2647.64,202.76 2647.64,251.97 2687.01,291.34 2992.13,291.34 3232.28,531.5 3604.33,531.5 3627.95,555.12 3663.39,555.12 3687.01,531.5 3720.47,531.5 3744.09,555.12 3779.53,555.12 3803.15,531.5 4236.22,531.5 4263.78,559.06 v1(4263.78,582.68)
  Bottom Layer w4.72: P9.28@4259.84,545.28 4259.84,578.74 v1(4263.78,582.68)
ECLK22P: IC1.B16 P9.27 pad.1@2352.36,127.95 | length 2376.1
  Top Layer w5.12: IC1.B16@2342.52,137.8 pad.1@2352.36,127.95
  M2 w4.72: pad.1@2352.36,127.95 2370.08,145.67 2399.61,145.67 2429.13,175.2 2429.13,263.78 2492.13,326.77 2545.28,326.77 2590.55,281.5 2629.92,281.5 2663.39,314.96 2964.57,314.96 3230.32,580.71 3269.69,580.71 3295.28,555.12 3332.68,555.12 3358.27,580.71 3389.76,580.71 3415.35,555.12 3448.82,555.12 3474.41,580.71 3513.78,580.71 3539.37,555.12 3572.83,555.12 3598.43,580.71 3807.09,580.71 3832.68,555.12 3860.24,555.12 3885.83,580.71 3919.29,580.71 3942.91,557.09 3978.35,557.09 4001.97,580.71 4039.37,580.71 4064.96,555.12 4092.52,555.12 4120.08,582.68 4147.64,582.68 4175.2,555.12 4228.35,555.12 4240.16,566.93 v1(4240.16,582.68)
  Bottom Layer w4.72: v1(4240.16,582.68) 4244.09,578.74 P9.27@4244.09,545.28
ECLK23N: IC1.A17 P7.40 pad.1@2372.05,167.32 | length 695.3
  Top Layer w5.12: IC1.A17@2362.2,157.48 pad.1@2372.05,167.32
  M2 w4.72: pad.1@2372.05,167.32 2393.7,188.98 2393.7,275.59 2472.44,354.33 2472.44,413.39 2582.68,523.62 2712.6,523.62 2736.22,547.24 v1(2736.22,582.68)
  Bottom Layer w4.72: P7.40@2732.28,545.28 2732.28,578.74 v1(2736.22,582.68)
ECLK23P: IC1.A16 P7.39 pad.1@2352.36,167.32 | length 695.9
  Top Layer w5.12: IC1.A16@2342.52,157.48 pad.1@2352.36,167.32
  M2 w4.72: pad.1@2352.36,167.32 2352.36,269.68 2440.94,358.27 2440.94,425.2 2566.93,551.18 2700.79,551.18 2712.6,562.99 v1(2712.6,582.68)
  Bottom Layer w4.72: v1(2712.6,582.68) 2716.54,578.74 P7.39@2716.54,545.28
ECLK24N: IC1.C15 P9.39 pad.1@2332.68,108.27 | length 2419.4
  Top Layer w5.12: IC1.C15@2322.83,118.11 pad.1@2332.68,108.27
  M2 w4.72: pad.1@2332.68,108.27 2604.33,108.27 2751.97,255.91 2775.59,255.91 2803.15,228.35 2854.33,228.35 2881.89,255.91 2913.39,255.91 2944.88,224.41 2976.38,224.41 3255.91,503.94 4263.78,503.94 4275.59,515.75 4299.21,515.75 4314.96,500 4366.14,500 4429.13,562.99 v1(4429.13,582.68)
  Bottom Layer w4.72: v1(4429.13,582.68) 4433.07,578.74 P9.39@4433.07,545.28
ECLK24P: IC1.C14 P9.40 pad.1@2312.99,108.27 | length 2417.7
  Top Layer w5.12: IC1.C14@2303.15,118.11 pad.1@2312.99,108.27
  M2 w4.72: pad.1@2312.99,108.27 2330.71,90.55 2625.98,90.55 2732.28,196.85 2996.06,196.85 3279.53,480.32 4374.02,480.32 4452.76,559.06 v1(4452.76,582.68)
  Bottom Layer w4.72: P9.40@4448.82,545.28 4448.82,578.74 v1(4452.76,582.68)
ECLK25N: IC1.A15 P7.28 pad.1@2313.07,167.32 | length 694.3
  Top Layer w5.12: pad.1@2313.07,167.32 IC1.A15@2322.83,157.48
  M2 w4.72: pad.1@2313.07,167.32 2312.99,167.4 2312.99,194.88 2295.28,212.6 2295.28,271.65 2314.96,291.34 2314.96,358.27 2295.28,377.95 2295.28,448.82 2366.14,519.68 2389.76,519.68 2413.39,496.06 2437.01,496.06 2460.63,519.68 2500,519.68 2547.24,566.93 v1(2547.24,582.68)
  Bottom Layer w4.72: P7.28@2543.31,545.28 2543.31,578.74 v1(2547.24,582.68)
ECLK25P: IC1.B15 P7.27 pad.1@2312.99,147.64 | length 695.8
  Top Layer w5.12: pad.1@2312.99,147.64 IC1.B15@2322.83,137.8
  M2 w4.72: pad.1@2312.99,147.64 2267.72,192.91 2267.72,468.5 2354.33,555.12 2496.06,555.12 v1(2523.62,582.68)
  Bottom Layer w4.72: v1(2523.62,582.68) 2527.56,578.74 P7.27@2527.56,545.28
ECLK26N: IC1.C5 P5.40 pad.1@2135.83,127.95 | length 1431.2
  Top Layer w5.12: IC1.C5@2125.98,118.11 pad.1@2135.83,127.95
  M2 w4.72: v1(1019.69,582.68) 1039.37,562.99 1826.77,562.99 2135.83,253.94 pad.1@2135.83,127.95
  Bottom Layer w4.72: P5.40@1015.75,545.28 1015.75,578.74 v1(1019.69,582.68)
ECLK26P: IC1.D5 P5.39 pad.1@2116.14,108.27 | length 1431.8
  Top Layer w5.12: pad.1@2116.14,108.27 IC1.D5@2125.98,98.43
  M2 w4.72: v1(996.06,582.68) 996.06,555.12 1007.87,543.31 1759.84,543.31 2116.14,187.01 pad.1@2116.14,108.27
  Bottom Layer w4.72: v1(996.06,582.68) 1000,578.74 P5.39@1000,545.28
ECLK27N: IC1.C4 P5.28 pad.1@2096.46,127.95 | length 1576.2
  Top Layer w5.12: pad.1@2096.46,127.95 IC1.C4@2106.3,118.11
  M2 w4.72: v1(830.71,582.68) 830.71,559.06 866.14,523.62 1385.83,523.62 1444.88,464.57 1507.87,464.57 1531.5,488.19 1588.58,488.19 1612.2,464.57 1665.35,464.57 1688.98,488.19 1763.78,488.19 2096.46,155.51 pad.1@2096.46,127.95
  Bottom Layer w4.72: P5.28@826.77,545.28 826.77,578.74 v1(830.71,582.68)
ECLK27P: IC1.D4 P5.27 pad.1@2096.46,88.58 | length 1576
  Top Layer w5.12: pad.1@2096.46,88.58 IC1.D4@2106.3,98.43
  M2 w4.72: v1(807.09,582.68) 807.09,539.37 842.52,503.94 1346.46,503.94 1492.13,358.27 1618.11,358.27 1661.27,315.11 1882.05,315.11 pad.1@2096.46,88.58
  Bottom Layer w4.72: v1(807.09,582.68) 811.02,578.74 P5.27@811.02,545.28
EDIN00N: IC1.U5 P6.34 | length 1693.3
  Top Layer w4.72: v1(807.09,-582.68) 807.09,-559.06 870.08,-496.06 996.06,-496.06 1015.75,-476.38 1070.87,-476.38 1090.55,-496.06 1122.05,-496.06 1200.79,-417.32 2086.61,-417.32 2116.14,-387.8 2116.14,-187.01 2125.98,-177.17 IC1.U5@2125.98,-157.48
  Bottom Layer w4.72: v1(807.09,-582.68) 811.02,-578.74 P6.34@811.02,-545.28
EDIN00P: IC1.T5 P6.33 | length 1695.1
  Top Layer w3: IC1.T5@2125.98,-137.79 2135.83,-147.64 2135.83,-167.32
  Top Layer w4.72: v1(830.71,-582.68) 830.71,-574.8 881.89,-523.62 1149.61,-523.62 1207.68,-465.55 2077.76,-465.55 2135.83,-407.48 2135.83,-167.32
  Bottom Layer w4.72: P6.33@826.77,-545.28 826.77,-578.74 v1(830.71,-582.68)
EDIN02N: IC1.U7 P6.25 | length 1610.4
  Top Layer w4.72: v1(948.82,-569.44) 948.82,-562.99 960.63,-551.18 1200.79,-551.18 1224.41,-527.56 1291.34,-527.56 1314.96,-551.18 1370.08,-551.18 1393.7,-527.56 1452.76,-527.56 1476.38,-551.18 2031.5,-551.18 2155.51,-427.17 2155.51,-167.32 IC1.U7@2165.35,-157.48
  Bottom Layer w4.72: v1(948.82,-569.44) 952.76,-569.44 P6.25@952.76,-545.28
EDIN02P: IC1.T7 P6.24 | length 1608.9
  Top Layer w3: IC1.T7@2165.35,-137.79 2175.2,-147.64 2175.2,-167.32
  Top Layer w4.72: v1(972.44,-569.44) 972.44,-574.8 980.31,-582.68 2039.37,-582.68 2175.2,-446.85 2175.2,-167.32
  Bottom Layer w4.72: P6.24@968.5,-545.28 968.5,-569.44 v1(972.44,-569.44)
EDIN10N: IC1.U11 P8.34 | length 730.1
  Top Layer w4.72: IC1.U11@2244.09,-157.48 2244.09,-181.1 2224.41,-200.79 2224.41,-496.06 2275.59,-547.24 2503.94,-547.24 2523.62,-566.93 v1(2523.62,-582.68)
  Bottom Layer w4.72: v1(2523.62,-582.68) 2527.56,-578.74 P8.34@2527.56,-545.28
EDIN10P: IC1.T11 P8.33 | length 730.6
  Top Layer w3: IC1.T11@2244.09,-137.79 2253.94,-147.64 2253.94,-167.32
  Top Layer w4.72: 2253.94,-167.32 2253.94,-196.85 2244.09,-206.69 2244.09,-444.88 2322.83,-523.62 2515.75,-523.62 2547.24,-555.12 v1(2547.24,-582.68)
  Bottom Layer w4.72: P8.33@2543.31,-545.28 2543.31,-578.74 v1(2547.24,-582.68)
EDIN12N: IC1.U13 P8.24 | length 816.7
  Top Layer w4.72: IC1.U13@2283.46,-157.48 2283.46,-423.23 2332.68,-472.44 2370.08,-472.44 2393.7,-448.82 2429.13,-448.82 2452.76,-472.44 2614.17,-472.44 2688.98,-547.24 v1(2688.98,-582.68)
  Bottom Layer w4.72: P8.24@2685.04,-545.28 2685.04,-578.74 v1(2688.98,-582.68)
EDIN12P: IC1.T13 P8.25 | length 815.2
  Top Layer w3: 2273.62,-167.32 2273.62,-147.64 IC1.T13@2283.46,-137.79
  Top Layer w4.72: 2273.62,-167.32 2273.62,-206.69 2263.78,-216.54 2263.78,-433.07 2326.77,-496.06 2594.49,-496.06 2665.35,-566.93 v1(2665.35,-582.68)
  Bottom Layer w4.72: v1(2665.35,-582.68) 2669.29,-578.74 P8.25@2669.29,-545.28
EDIN20N: IC1.P17 P10.34 | length 2182.2
  Top Layer w4.72: IC1.P17@2362.2,-98.42 2372.05,-108.27 2391.73,-108.27 2568.9,-285.43 2864.17,-285.43 3139.76,-561.02 3368.11,-561.02 3421.26,-614.17 3480.32,-614.17 3496.06,-598.43 3566.93,-598.43 3582.68,-614.17 3661.42,-614.17 3681.1,-594.49 3736.22,-594.49 3755.91,-614.17 4224.41,-614.17 4240.16,-598.43 v1(4240.16,-582.68)
  Bottom Layer w4.72: v1(4240.16,-582.68) 4244.09,-578.74 P10.34@4244.09,-545.28
EDIN20P: IC1.P16 P10.33 | length 2180.6
  Top Layer w3: IC1.P16@2342.52,-98.42 2352.36,-88.58 2372.05,-88.58
  Top Layer w4.72: 2372.05,-88.58 2401.57,-88.58 2578.74,-265.75 2893.7,-265.75 3159.45,-531.5 3421.26,-531.5 3444.88,-555.12 4255.91,-555.12 4263.78,-562.99 v1(4263.78,-582.68)
  Bottom Layer w4.72: P10.33@4259.84,-545.28 4259.84,-578.74 v1(4263.78,-582.68)
EDIN22N: IC1.M17 P10.25 | length 2349.1
  Top Layer w4.72: IC1.M17@2362.2,-59.05 2372.05,-68.9 2411.42,-68.9 2588.58,-246.06 2923.23,-246.06 3177.17,-500 3519.69,-500 3539.37,-519.68 3598.43,-519.68 3618.11,-500 3681.1,-500 3700.79,-519.68 3751.97,-519.68 3771.65,-500 3814.96,-500 3834.65,-519.68 3877.95,-519.68 3897.64,-500 3940.94,-500 3956.69,-515.75 4007.87,-515.75 4023.62,-500 4318.9,-500 4381.89,-562.99 v1(4381.89,-582.68)
  Bottom Layer w4.72: v1(4381.89,-582.68) 4385.83,-578.74 P10.25@4385.83,-545.28
EDIN22P: IC1.M16 P10.24 | length 2347.8
  Top Layer w3: IC1.M16@2342.52,-59.05 2352.36,-49.21 2372.05,-49.21
  Top Layer w4.72: 2372.05,-49.21 2421.26,-49.21 2598.43,-226.38 2952.76,-226.38 3198.82,-472.44 4330.71,-472.44 4405.51,-547.24 v1(4405.51,-582.68)
  Bottom Layer w4.72: P10.24@4401.57,-545.28 4401.57,-578.74 v1(4405.51,-582.68)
